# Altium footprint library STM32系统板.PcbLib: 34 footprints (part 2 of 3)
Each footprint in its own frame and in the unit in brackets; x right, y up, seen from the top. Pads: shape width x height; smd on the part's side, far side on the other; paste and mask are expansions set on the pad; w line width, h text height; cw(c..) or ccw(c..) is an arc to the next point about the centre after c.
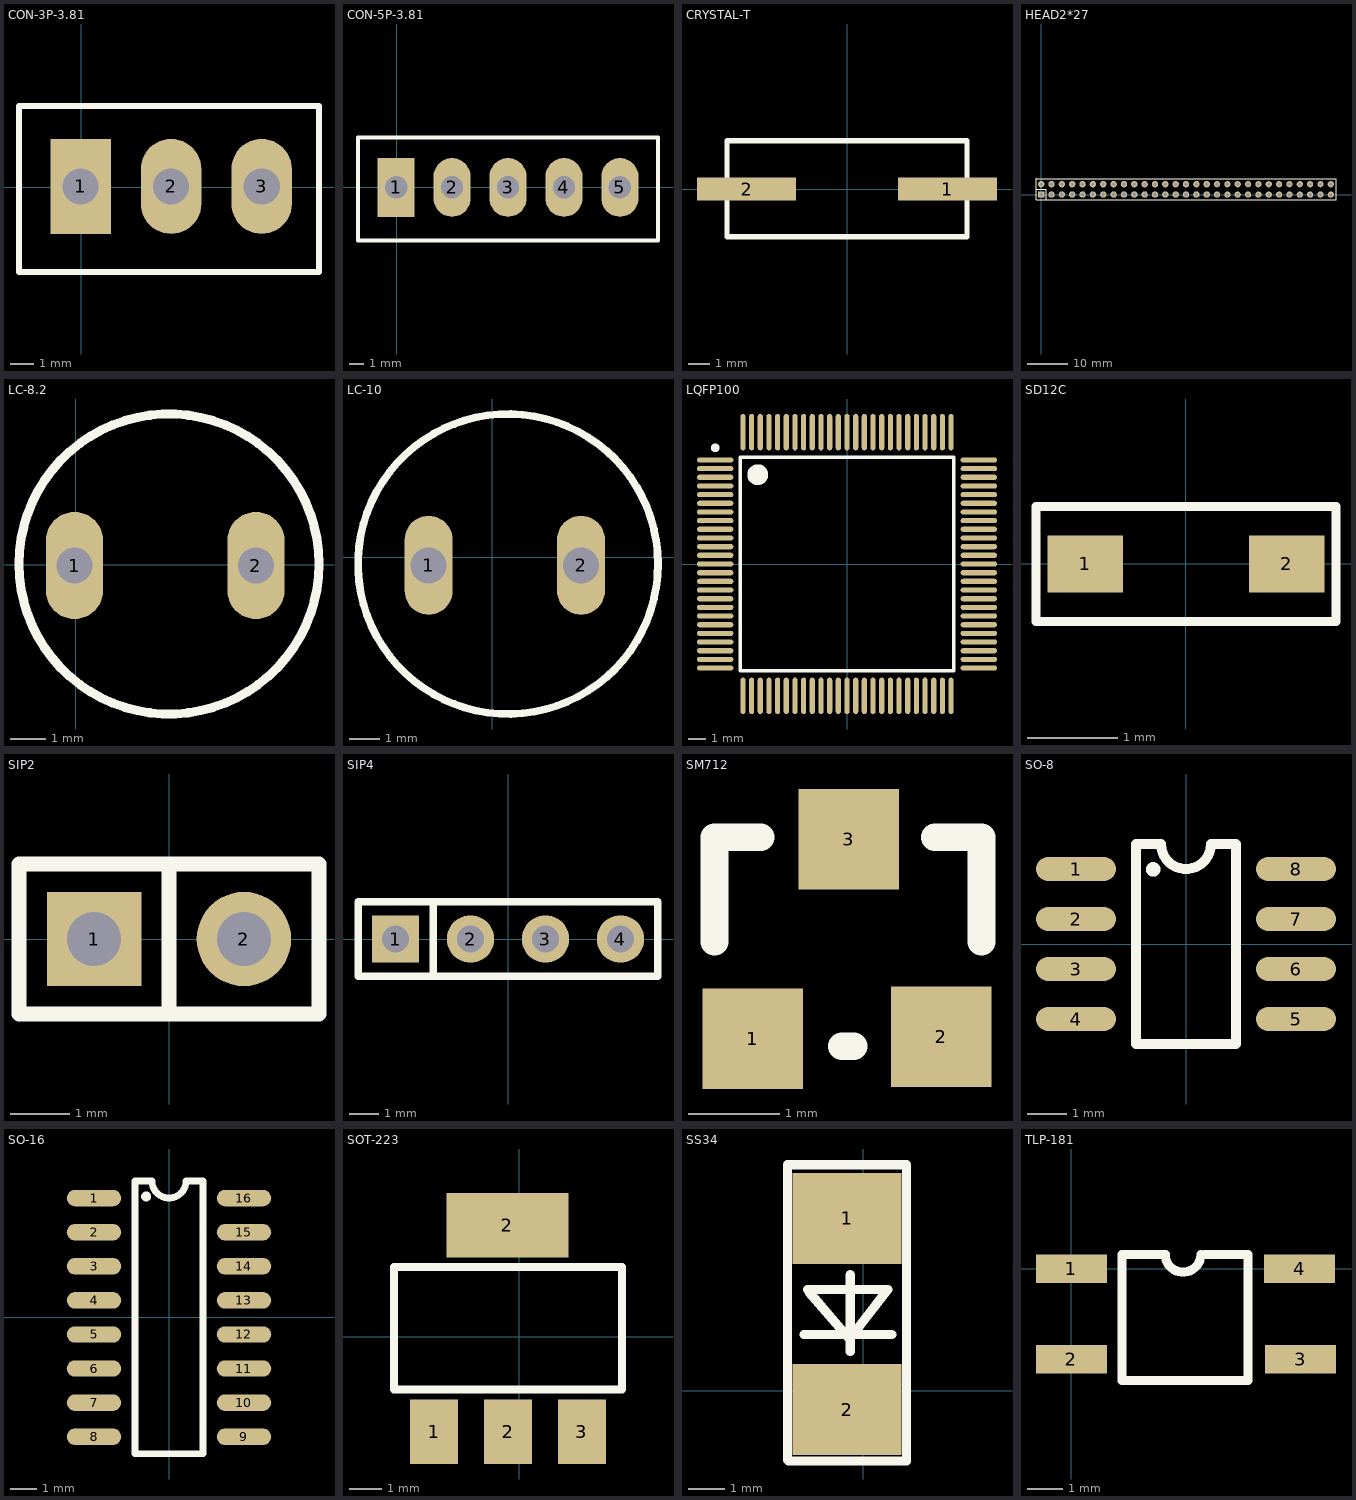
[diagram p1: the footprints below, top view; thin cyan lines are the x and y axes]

## CON-3P-3.81 [mil]
pads (3):
  rect 100x157.48 hole 60: 1(-1,1)
  oval 100x157.48 hole 60: 2(149,1) 3(299,1)
Top Overlay:
  lines w10: -103,-141 -103,134.59 394,134.59 394,-141 -103,-141

## CON-5P-3.81 [mil]
pads (5):
  rect 100x157.48 hole 60: 1(-2,0)
  oval 100x157.48 hole 60: 2(148,0) 3(298,0) 4(448,0) 5(598,0)
Top Overlay:
  lines w10: -104,-142 700,-142 700,133.59 -104,133.59 -104,-142

## CRYSTAL-T [mm]
pads (2):
  rect 4.65x1.1 smd: 1(4.705,0) 2(-4.705,0)
Top Overlay:
  lines w0.254: -5.625,-2.24 5.625,-2.24 5.625,2.26 -5.625,2.26 -5.625,-2.24

## HEAD2*27 [mil]
height 62.99
pads (58):
  rect 62x62 hole 35: 1(0.42,0.42)
  round 62 hole 35: 2(0.42,100.42) 3(100.42,0.42) 4(100.42,100.42) 5(200.43,0.42) 6(200.43,100.42) 7(300.43,0.42) 8(300.43,100.42) 9(400.43,0.42) 10(400.43,100.42) 11(500.43,0.42) 12(500.43,100.42) 13(600.42,0.42) 14(600.42,100.42) 15(700.42,0.42) 16(700.42,100.42) 17(800.42,0.42) 18(800.42,100.42) 19(900.42,0.42) 20(900.42,100.42) 21(1000.42,0.42) 22(1000.42,100.42) 23(1100.42,0.42) 24(1100.42,100.42) 25(1200.42,0.42) 26(1200.42,100.42) 27(1300.42,0.42) 28(1300.42,100.42) 29(1400.42,0.42) 30(1400.42,100.42) 31(1500.42,0.42) 32(1500.42,100.42) 33(1600.42,0.42) 34(1600.42,100.42)
  round 60 hole 35: 35(1700,0) 36(1700,100) 37(1800,0) 38(1800,100) 39(1900,0) 40(1900,100) 41(2000,0) 42(2000,100) 43(2100,0) 44(2100,100) 45(2200,0) 46(2200,100) 47(2300,0) 48(2300,100) 49(2400,0) 50(2400,100) 51(2500,0) 52(2500,100) 53(2600,0) 54(2600,100) 55(2700,0) 56(2700,100) 57(2800,0) 58(2800,100)
Top Overlay:
  lines w7: -49.58,51.18 51.18,51.18 51.18,-49.58 ; -47.97,152.48 2850,155 2850,-49.58 1650.42,-49.58 -49.58,-49.58 -49.58,150.43 -49.58,155.87 -47.97,157.48

## LC-8.2 [mm]
pads (2):
  oval 1.6x3 hole 1: 1(-0.034,-0.017) 2(5.046,-0.017)
Top Overlay:
  circle w0.254: c2.612,0.025 r4.2

## LC-10 [mm]
height 12
pads (2):
  oval 1.6x3.3 hole 1.2: 1(-2.117,-0.271) 2(2.963,-0.271)
Top Overlay:
  circle w0.254: c0.529,-0.229 r5

## LQFP100 [mm]
height 12
pads (100):
  oval 2.1x0.3 smd: 1(-7.6,6) 2(-7.6,5.5) 3(-7.6,5) 4(-7.6,4.5) 5(-7.6,4) 6(-7.6,3.5) 7(-7.6,3) 8(-7.6,2.5) 9(-7.6,2) 10(-7.6,1.5) 11(-7.6,1) 12(-7.6,0.5) 13(-7.6,0) 14(-7.6,-0.5) 15(-7.6,-1) 16(-7.6,-1.5) 17(-7.6,-2) 18(-7.6,-2.5) 19(-7.6,-3) 20(-7.6,-3.5) 21(-7.6,-4) 22(-7.6,-4.5) 23(-7.6,-5) 24(-7.6,-5.5) 25(-7.6,-6) 51(7.6,-6) 52(7.6,-5.5) 53(7.6,-5) 54(7.6,-4.5) 55(7.6,-4) 56(7.6,-3.5) 57(7.6,-3) 58(7.6,-2.5) 59(7.6,-2) 60(7.6,-1.5) 61(7.6,-1) 62(7.6,-0.5) 63(7.6,0) 64(7.6,0.5) 65(7.6,1) 66(7.6,1.5) 67(7.6,2) 68(7.6,2.5) 69(7.6,3) 70(7.6,3.5) 71(7.6,4) 72(7.6,4.5) 73(7.6,5) 74(7.6,5.5) 75(7.6,6)
  oval 0.3x2.1 smd: 26(-6,-7.6) 27(-5.5,-7.6) 28(-5,-7.6) 29(-4.5,-7.6) 30(-4,-7.6) 31(-3.5,-7.6) 32(-3,-7.6) 33(-2.5,-7.6) 34(-2,-7.6) 35(-1.5,-7.6) 36(-1,-7.6) 37(-0.5,-7.6) 38(0,-7.6) 39(0.5,-7.6) 40(1,-7.6) 41(1.5,-7.6) 42(2,-7.6) 43(2.5,-7.6) 44(3,-7.6) 45(3.5,-7.6) 46(4,-7.6) 47(4.5,-7.6) 48(5,-7.6) 49(5.5,-7.6) 50(6,-7.6) 76(6,7.6) 77(5.5,7.6) 78(5,7.6) 79(4.5,7.6) 80(4,7.6) 81(3.5,7.6) 82(3,7.6) 83(2.5,7.6) 84(2,7.6) 85(1.5,7.6) 86(1,7.6) 87(0.5,7.6) 88(0,7.6) 89(-0.5,7.6) 90(-1,7.6) 91(-1.5,7.6) 92(-2,7.6) 93(-2.5,7.6) 94(-3,7.6) 95(-3.5,7.6) 96(-4,7.6) 97(-4.5,7.6) 98(-5,7.6) 99(-5.5,7.6) 100(-6,7.6)
Top Overlay:
  circle w0.6: c-5.15,5.15 r0.3
  circle w0.25: c-7.6,6.7 r0.125
  lines w0.2: -6.15,-6.15 6.15,-6.15 6.15,6.15 -6.15,6.15 -6.15,-6.15

## SD12C [mm]
pads (2):
  rect 0.83x0.63 smd: 1(-1.11,0) 2(1.11,0)
Top Overlay:
  lines w0.1: -1.651,-0.635 -1.651,0.635 1.651,0.635 1.651,-0.635 -1.651,-0.635

## SIP2 [mil]
pads (2):
  rect 63x63 hole 36: 1(-50,0)
  round 63 hole 36: 2(50,0)
Top Overlay:
  lines w10: 0,-50 0,50 ; -100,-50 100,-50 100,50 -100,50 -100,-50

## SIP4 [mil]
pads (4):
  rect 63x63 hole 36: 1(-150,0)
  round 63 hole 36: 2(-50,0) 3(50,0) 4(150,0)
Top Overlay:
  lines w10: -100,-50 -100,50 ; -200,-50 200,-50 200,50 -200,50 -200,-50

## SM712 [mm]
pads (3):
  rect 1.1x1.1 smd: 1(1.068,0.743) 2(3.128,0.763) 3(2.118,2.923)
Top Overlay:
  lines w0.305: 0.648,1.803 0.648,2.946 1.156,2.946 ; 2.045,0.66 2.172,0.66 ; 3.061,2.946 3.569,2.946 3.569,1.803

## SO-8 [mil]
pads (8):
  oval 80x24 smd: 1(-110,75) 2(-110,25) 3(-110,-25) 4(-110,-75) 5(110,-75) 6(110,-25) 7(110,25) 8(110,75)
Top Overlay:
  circle w10: c-32.77,74.61 r2.3
  lines w10: -50,-100 -50,100 -25,100 ccw(c0,100) 25,100 50,100 50,-100 -50,-100

## SO-16 [mil]
pads (16):
  oval 80x24 smd: 1(-110,175) 2(-110,125) 3(-110,75) 4(-110,25) 5(-110,-25) 6(-110,-75) 7(-110,-125) 8(-110,-175) 9(110,-175) 10(110,-125) 11(110,-75) 12(110,-25) 13(110,25) 14(110,75) 15(110,125) 16(110,175)
Top Overlay:
  circle w10: c-33.56,177.36 r2.3
  lines w10: -50,-200 50,-200 50,200 25,200 cw(c0,200) -25,200 -50,200 -50,-200

## SOT-223 [mil]
pads (4):
  rect 59x79 smd: 1(-104.55,-116.77) 2(-14,-116.77) 3(76.55,-116.77)
  rect 150x79 smd: 2(-14.67,136.77)
Top Overlay:
  lines w10: -154,-64.77 -154,85.23 126,85.23 126,-64.77 -154,-64.77

## SS34 [mm]
pads (2):
  rect 3x2.5 smd: 1(-0.44,4.743) 2(-0.44,-0.516)
Top Overlay:
  lines w0.254: -2.083,-1.905 -2.083,6.223 1.194,6.223 1.194,-1.93 -2.057,-1.93 ; -1.626,1.549 0.787,1.549 ; -1.53,2.786 0.676,2.786 -0.287,1.542 ; -1.483,2.711 -0.387,1.441 ; -0.356,1.082 -0.356,3.193

## TLP-181 [mm]
pads (4):
  rect 2x0.8 smd: 1(0,0) 2(0,-2.54) 3(6.452,-2.54) 4(6.426,0)
Top Overlay:
  lines w0.254: 3.642,0.406 cw(c3.142,0.406) 2.642,0.406 1.422,0.406 1.422,-3.15 4.978,-3.15 4.978,0.406 3.759,0.406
